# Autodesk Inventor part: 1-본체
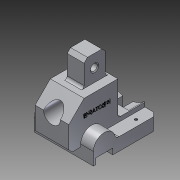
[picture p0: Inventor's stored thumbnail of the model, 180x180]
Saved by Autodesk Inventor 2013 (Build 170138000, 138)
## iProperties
Created: 2016-11
Part Number: 1-본체
Material: 알루미늄 6061
Document SubType Name: Modeling
Designer: cad22
Density: 2.71 g/cm^3
Mass: 462.908 g
Surface Area: 317.29 cm^2
Volume: 170.815 cm^3
Author: cad22
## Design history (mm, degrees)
sketch "스케치1"
  geometry: L1 (-29, 6)-(-11, 24); L2 (-11, 24)-(29, 24); L3 (29, 24)-(29, -16); L4 (-29, 6)-(-29, -24); L5 (-29, -24)-(29, -24); L6 (61, -16)-(29, -16); L7 (29, -36)-(61, -36); L8 (61, -36)-(61, -16); L9 (29, -36)-(29, -24); 3 further points
  constraints: 18 end point, 4 perpendicular, 2 parallel, 1 horizontal, 1 horizontal alignment, 1 midpoint, 1 point on line, 1 vertical alignment
  dimensions: "d0" = 45 deg angle of L2 L1; "d1" = 18 distance from line of L1.end L4; "d3" = 58 distance between parallel lines of L3 L4; "d125" = 48 distance between parallel lines of L5 L2; "d151" = 60 distance between parallel lines of L2 L7; "d152" = 20 distance between parallel lines of L6 L7; "d153" = 90 distance between parallel lines of L4 L8; "d154" = 32 distance between parallel lines of L8 L9; "d155" = 36 distance from line of point (0, 0) L7
extrude "돌출1" new body sketch "스케치1" stored distance "d8" = 40; taper "d9" = 0 deg
chamfer "모따기1" distance "d47" = 4; stored, may be unused: second distance "d48" = 2, angle "d49" = 45 deg
sketch "스케치5"
  geometry: L1 (-15, -21)-(-15, -36); L2 (-15, -36)-(-12, -36); L3 (-12, -29)-(-12, -36); L4 (-12, -29)-(8, -29); L5 (8, -29)-(8, -36); L6 (8, -36)-(61, -36); L7 (61, -36)-(61, -21); L8 (61, -21)-(11, -21); L9 (29, -16)-(61, -16) reference; L10 (-11, 24)-(29, 24) reference; A1 r 13 centre (-2, -21) between (11, -21) and (-15, -21); 1 further point
  constraints: 16 end point, 6 perpendicular, 2 point on circle, 1 centre point, 1 parallel, 1 tangent, 1 vertical
  dimensions: "d38" = 20 distance of L3.start L4.end; "d39" = 3 distance of L1.end L2.end; "d40" = 7 distance of L3.start L2.end; "d41" = 7 distance of L4.end L5.end; "d42" = 63 distance from line of L7 A1.centre; "d43" = 13 radius of A1; "d134" = 60 distance between parallel lines of L10 L6; "d135" = 15 distance between parallel lines of L6 L8; "d167" = 0 distance from line of L9.end L7; "d168" = 5 distance from line of A1.centre L9
extrude "돌출2" join sketch "스케치5" stored distance "d45" = 70; taper "d46" = 0 deg
sketch "스케치7"
  geometry: L1 (-11, 24)-(29, 24) reference; L2 (29, 24)-(29, -16) reference; L3 (-1, 24)-(-1, 54); L4 (-1, 54)-(24, 54); L5 (24, 54)-(24, 24); L6 (61, -36)-(8, -36) reference; 2 further points
  constraints: 6 end point, 2 perpendicular, 2 point on line, 1 midpoint, 1 parallel
  dimensions: "d61" = 5 distance between parallel lines of L5 L2; "d62" = 90 distance between parallel lines of L6 L4; "d63" = 25 distance of L3.end L4.end
extrude "돌출3" join sketch "스케치7" stored distance "d65" = 20; taper "d66" = 0 deg
sketch "스케치8"
  geometry: L1 (-54, -1)-(-24, -1) reference; L2 (-24, 24)-(-54, 24) reference; 3 further points
  constraints: 1 midpoint, 1 vertical alignment
  dimensions: "d71" = 12.5 distance from line of L1 point (-39, 11.5)
hole "구멍2" sketch "스케치8" at (-39, 11.5) diameter "d72" = 8; stored, may be unused: countersink angle "d76" = 90 deg, drill point angle "d78" = 118 deg; dims "d73" = 6, "d74" = 28, "d75" = 7, "d77" = 8
chamfer "모따기4" distance "d79" = 1; stored, may be unused: second distance "d80" = 2, angle "d81" = 45 deg
sketch "스케치11"
  geometry: L1 (-55, 50)-(15, 50) reference; 4 further points
  constraints: 1 point on line, 1 vertical alignment
  dimensions: "d93" = 18 distance from line of point (7.5, 32) L1
hole "구멍3" sketch "스케치11" at (7.5, 32) diameter "d94" = 3.242; stored, may be unused: countersink angle "d98" = 90 deg, drill point angle "d100" = 118 deg; dims "d95" = 6, "d96" = 28, "d97" = 7, "d99" = 8
chamfer "모따기5" distance "d101" = 5; stored, may be unused: second distance "d102" = 2, angle "d103" = 45 deg
node "작업 평면1"
sketch "스케치12"
  geometry: L1 (-24, 29)-(-24, -11) reference; L2 (16, 29)-(-24, 29) reference; 2 further points
  constraints: 1 other
  dimensions: "d105" = 18 distance from line of L1 point (-6, 4); "d106" = 25 distance from line of L2 point (-6, 4)
feature "엠보싱1" sketch "스케치12" dims "d0" = 45 deg, "d1" = 18, "d3" = 58, "d107" = 0.5, "d108" = 0, "d125" = 48, "d151" = 60, "d152" = 20, "d153" = 90, "d154" = 32, "d155" = 36
fillet "모깎기1" dims "d109" = 5
fillet "모깎기2" dims "d110" = 3
chamfer "모따기7" distance "d136" = 4; stored, may be unused: second distance "d137" = 2, angle "d138" = 45 deg
sketch "스케치14"
  geometry: L1 (40, 37)-(40, 0) reference; L2 (-15, 60)-(55, 60) reference; 2 further points
  dimensions: "d165" = 42 distance from line of L2 point (20, 18); "d166" = 20 distance from line of point (20, 18) L1
hole "구멍6" sketch "스케치14" at (20, 18) diameter "d141" = 20; stored, may be unused: countersink angle "d145" = 90 deg, drill point angle "d147" = 118 deg; dims "d142" = 6, "d143" = 29, "d144" = 7, "d146" = 8
chamfer "모따기8" distance "d148" = 1; stored, may be unused: second distance "d149" = 2, angle "d150" = 45 deg
sketch "스케치15"
  geometry: C1 r 14.5 at (20, -22) reference; C2 r 11 at (20, -22) reference; C3 r 29 at (20, -22); 1 further point
  constraints: 1 centre point, 1 coincident
  dimensions: "d156" = 58 diameter of C3
extrude "돌출7" cut sketch "스케치15" distance "d158" = 18; taper "d159" = 0 deg
sketch "스케치16"
  geometry: L1 (10, 20)-(-50, 20) reference; L2 (-26, 0)-(-14, 0); L3 (-14, 0)-(-14, 20); L4 (-14, 20)-(-26, 20); L5 (-26, 20)-(-26, 0); 2 further points
  constraints: 8 end point, 2 midpoint, 2 parallel, 1 horizontal, 1 perpendicular
  dimensions: "d160" = 12 distance of L3.end L4.end; "d162" = 20 distance between parallel lines of L2 L4
extrude "돌출8" cut sketch "스케치16" distance "d163" = 18; taper "d164" = 0 deg
node "솔리드1"
mirror "대칭1"
node "투영된 루프1"
other parameters: "d104" = 8
